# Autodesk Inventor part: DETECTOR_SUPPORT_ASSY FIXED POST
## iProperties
Shininess: 64.0
Length Units: 11272
Angle Units: 11279
Time Units: 11290
Mass Units: 11286
Length Display Precision: 3
Angle Display Precision: 2
Compacted: True
Part Number: DETECTOR_SUPPORT_ASSY FIXED POST
Document SubType Name: Modeling
Created: 2004-08
Designer: John Blackburn
Material: BRASS, SOFT YELLOW BRASS
Manufacturer: Standard
Standards Organization: Custom
Density: 0.0
Volumn: 0.0
Area: 0.0
PropertySet Name: Model Information
Control State: 0
Master: False
Checked Out: False
Author: John Blackburn
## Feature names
1. ExtrusionBlind1
2. Hole1
